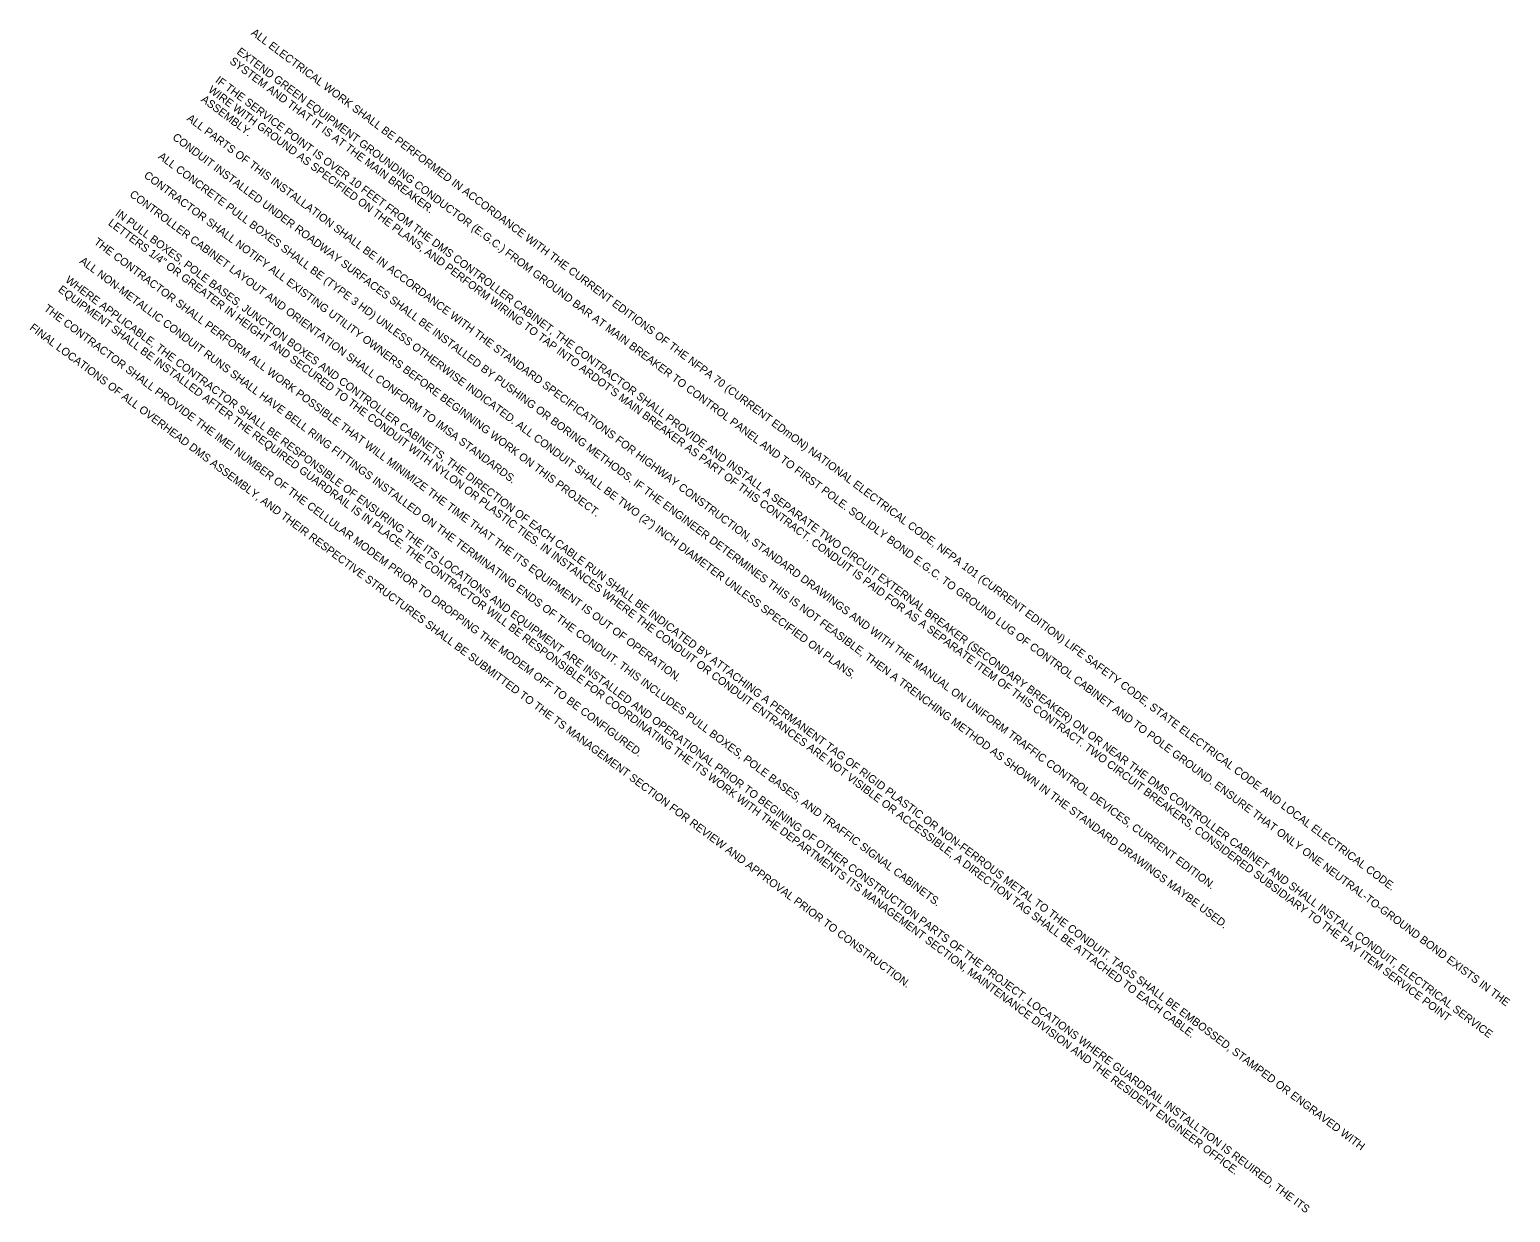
# Model space of a CAD drawing. Extents: x 626494 to 628870, y 365986 to 369334.
# Drawn here: x 627373 to 628045, y 365986 to 366522 of the extents above; entities that cross this region are included whole.
import ezdxf

# ---------------------------------------------------------------- set-up
doc = ezdxf.new("R2010")
doc.units = 0
doc.layers.add('R_Shade Frontage Road', color=7, linetype='Continuous')

msp = doc.modelspace()

# ---------------------------------------------------------------- texts
at = {"layer": 'R_Shade Frontage Road'}
for s, p in [('ALL ELECTRICAL WORK SHALL BE PERFORMED IN ACCORDANCE WITH THE CURRENT EDITIONS OF THE NFPA 70 (CURRENT EDmON) NATIONAL ELECTRICAL CODE, NFPA 101 (CURRENT EDITION) LIFE SAFETY CODE, STATE ELECTRICAL CODE AND LOCAL ELECTRICAL CODE.', (627473.58, 366520.39)), ('EXTEND GREEN EQUIPMENT GROUNDING CONDUCTOR (E.G.C.) FROM GROUND BAR AT MAIN BREAKER TO CONTROL PANEL AND TO FIRST POLE. SOLIDLY BOND E.G.C. TO GROUND LUG OF CONTROL CABINET AND TO POLE GROUND. ENSURE THAT ONLY ONE NEUTRAL-TO-GROUND BOND EXISTS IN THE ', (627467.1, 366511.75)), ('SYSTEM AND THAT IT IS AT THE MAIN BREAKER.', (627463.85, 366507.44)), ('IF THE SERVICE POINT IS OVER 10 FEET FROM THE DMS CONTROLLER CABINET, THE CONTRACTOR SHALL PROVIDE AND INSTALL A SEPARATE TWO CIRCUIT EXTERNAL BREAKER (SECONDARY BREAKER) ON OR NEAR THE DMS CONTROLLER CABINET AND SHALL INSTALL CONDUIT, ELECTRICAL SERVICE ', (627457.37, 366498.8)), ("WIRE WITH GROUND AS SPECIFIED ON THE PLANS, AND PERFORM WIRING TO TAP INTO ARDOT'S MAIN BREAKER AS PART OF THIS CONTRACT. CONDUIT IS PAID FOR AS A SEPARATE ITEM OF THIS CONTRACT. TWO CIRCUIT BREAKERS, CONSIDERED SUBSIDIARY TO THE PAY ITEM SERVICE POINT ", (627454.13, 366494.48)), ('ASSEMBLY. ', (627450.88, 366490.16)), ('ALL PARTS OF THIS INSTALLATION SHALL BE IN ACCORDANCE WITH THE STANDARD SPECIFICATIONS FOR HIGHWAY CONSTRUCTION, STANDARD DRAWINGS AND WITH THE MANUAL ON UNIFORM TRAFFIC CONTROL DEVICES, CURRENT EDITION.', (627444.4, 366481.53)), ('CONDUIT INSTALLED UNDER ROADWAY SURFACES SHALL BE INSTALLED BY PUSHING OR BORING METHODS. IF THE ENGINEER DETERMINES THIS IS NOT FEASIBLE, THEN A TRENCHING METHOD AS SHOWN IN THE STANDARD DRAWINGS MAYBE USED.', (627437.91, 366472.89)), ('ALL CONCRETE PULL BOXES SHALL BE (TYPE 3 HD) UNLESS OTHERWISE INDICATED. ALL CONDUIT SHALL BE TWO (2”) INCH DIAMETER UNLESS SPECIFIED ON PLANS.', (627431.43, 366464.26)), ('CONTRACTOR SHALL NOTIFY ALL EXISTING UTILITY OWNERS BEFORE BEGINNING WORK ON THIS PROJECT. ', (627424.94, 366455.62)), ('CONTROLLER CABINET LAYOUT AND ORIENTATION SHALL CONFORM TO IMSA STANDARDS.', (627418.46, 366446.98)), ('IN PULL BOXES, POLE BASES, JUNCTION BOXES AND CONTROLLER CABINETS, THE DIRECTION OF EACH CABLE RUN SHALL BE INDICATED BY ATTACHING A PERMANENT TAG OF RIGID PLASTIC OR NON-FERROUS METAL TO THE CONDUIT. TAGS SHALL BE EMBOSSED, STAMPED OR ENGRAVED WITH ', (627411.97, 366438.35)), ('LETTERS 1/4" OR GREATER IN HEIGHT AND SECURED TO THE CONDUIT WITH NYLON OR PLASTIC TIES. IN INSTANCES WHERE THE CONDUIT OR CONDUIT ENTRANCES ARE NOT VISIBLE OR ACCESSIBLE, A DIRECTION TAG SHALL BE ATTACHED TO EACH CABLE.', (627408.73, 366434.03)), ('THE CONTRACTOR SHALL PERFORM ALL WORK POSSIBLE THAT WILL MINIMIZE THE TIME THAT THE ITS EQUIPMENT IS OUT OF OPERATION.', (627402.25, 366425.39)), ('ALL NON-METALLIC CONDUIT RUNS SHALL HAVE BELL RING FITTINGS INSTALLED ON THE TERMINATING ENDS OF THE CONDUIT. THIS INCLUDES PULL BOXES, POLE BASES, AND TRAFFIC SIGNAL CABINETS.', (627395.76, 366416.76)), ('EQUIPMENT SHALL BE INSTALLED AFTER THE REQUIRED GUARDRAIL IS IN PLACE. THE CONTRACTOR WILL BE RESPONSIBLE FOR COORDINATING THE ITS WORK WITH THE DEPARTMENTS ITS MANAGEMENT SECTION, MAINTENANCE DIVISION AND THE RESIDENT ENGINEER OFFICE.', (627386.03, 366403.8)), ('WHERE APPLICABLE, THE CONTRACTOR SHALL BE RESPONSIBLE OF ENSURING THE ITS LOCATIONS AND EQUIPMENT ARE INSTALLED AND OPERATIONAL PRIOR TO BEGINING OF OTHER CONSTRUCTION PARTS OF THE PROJECT. LOCATIONS WHERE GUARDRAIL INSTALLTION IS REUIRED, THE ITS ', (627389.28, 366408.12)), ('THE CONTRACTOR SHALL PROVIDE THE IMEI NUMBER OF THE CELLULAR MODEM PRIOR TO DROPPING THE MODEM OFF TO BE CONFIGURED. ', (627379.55, 366395.17)), ('FINAL LOCATIONS OF ALL OVERHEAD DMS ASSEMBLY, AND THEIR RESPECTIVE STRUCTURES SHALL BE SUBMITTED TO THE TS MANAGEMENT SECTION FOR REVIEW AND APPROVAL PRIOR TO CONSTRUCTION.', (627373.06, 366386.53))]:
    msp.add_text(s, height=3.6, rotation=323.09678, dxfattribs=at).set_placement(p)

doc.saveas('drawing.dxf')
